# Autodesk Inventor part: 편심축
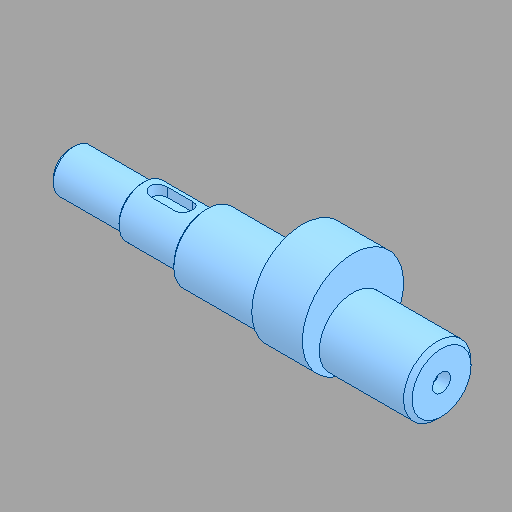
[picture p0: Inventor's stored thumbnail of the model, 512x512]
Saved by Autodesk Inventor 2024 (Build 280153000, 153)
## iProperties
Created: 2025-02
Part Number: 편심축
Material: 강철, 탄소
Document SubType Name: Modeling
Designer: kh_501
Density: 7.85 g/cm^3
Appearance: 기본값
Author: jhkim
Sending System: Autodesk Inventor 2025
Preprocessor: ST-DEVELOPER v20
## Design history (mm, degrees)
feature "솔리드1"
node "솔리드2"
